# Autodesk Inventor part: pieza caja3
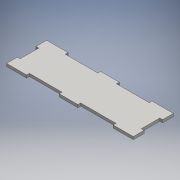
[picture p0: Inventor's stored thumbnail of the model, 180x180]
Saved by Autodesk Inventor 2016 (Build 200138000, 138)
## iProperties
Created: 2016-06
Part Number: pieza caja3
Material: Genérico
Document SubType Name: Modeling
Designer: adm
Density: 1 g/cm^3
Appearance: Valor por defecto
Author: adm
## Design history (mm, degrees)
sketch "Boceto1"
  geometry: L1 (-68, -21.5)-(68, 21.5); L2 (68, -21.5)-(-68, 21.5); L3 (65, 10)-(65, -10); L4 (-65, -10)-(-65, 10); L5 (-10, 21.5)-(-10, 18.5); L6 (10, 21.5)-(10, 18.5); L7 (-45, 21.5)-(-45, 18.5); L8 (8.5, -21.5)-(8.5, -18.5); L9 (-11.5, -21.5)-(-11.5, -18.5); L10 (45, 21.5)-(45, 18.5); L11 (-45, 21.5)-(-68, 21.5); L12 (68, 21.5)-(45, 21.5); L13 (10, 21.5)-(-10, 21.5); L14 (10, 18.5)-(45, 18.5); L15 (-68, -21.5)-(-46.5, -21.5); L16 (-11.5, -18.5)-(-46.5, -18.5); L17 (-11.5, -21.5)-(8.5, -21.5); L18 (46.5, -21.5)-(68, -21.5); L19 (46.5, -21.5)-(46.5, -18.5); L20 (43.731, -13.827)-(43.722, -12.491); L21 (-46.5, -21.5)-(-46.5, -18.5); L22 (-46.455, -14.688)-(-46.447, -13.352); L23 (-68, 10)-(-65, 10); L24 (-68, 21.5)-(-68, 10); L25 (-68, -10)-(-68, -21.5); L26 (-68, -10)-(-65, -10); L27 (68, 10)-(65, 10); L28 (68, -10)-(65, -10); L29 (68, -21.5)-(68, -10); L30 (68, 10)-(68, 21.5); L31 (-45, 18.5)-(-10, 18.5); L32 (46.5, -18.5)-(8.5, -18.5); 19 further points
  constraints: 64 end point, 20 parallel, 12 perpendicular, 3 horizontal, 3 midpoint, 2 point on line
  dimensions: "d0" = 136 distance of L2.end L1.end; "d14" = 43 distance between parallel lines of L18 L12; "d15" = 43 distance between parallel lines of L15 L11; "d16" = 3 distance between parallel lines of L30 L3; "d17" = 3 distance between parallel lines of L4 L24; "d18" = 3 distance between parallel lines of L25 L4; "d19" = 3 distance between parallel lines of L29 L3; "d20" = 3 distance between parallel lines of L31 L11; "d21" = 35 distance between parallel lines of L5 L7; "d22" = 35 distance between parallel lines of L10 L6
extrude "Extrusión1" new body sketch "Boceto1" distance "d12" = 3; taper "d13" = 0 deg
node "Sólido1"
other parameters: "d2" = 3, "d5" = 35
